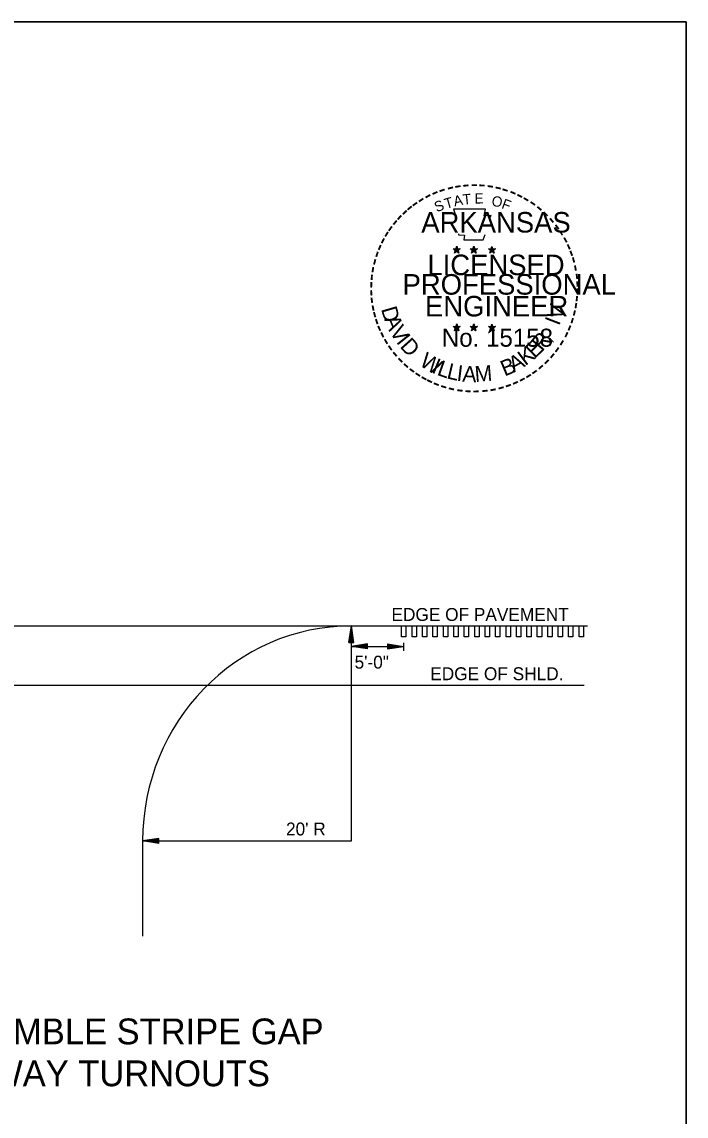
# Model space of a CAD drawing. Extents: x 28704 to 32542, y 50360 to 59122.
# Drawn here: x 30070 to 30404, y 50922 to 51472 of the extents above; entities that cross this region are included whole.
import ezdxf

# ---------------------------------------------------------------- set-up
doc = ezdxf.new("R2010")
doc.units = 0
for name, color, linetype in [('Default', 7, 'Continuous'), ('R_Alt Surface', 7, 'Continuous'), ('R_Alt Surface Annot', 7, 'Continuous'), ('R_Border Prem', 7, 'Continuous')]:
    doc.layers.add(name, color=color, linetype=linetype)

msp = doc.modelspace()

# ---------------------------------------------------------------- linework, layer by layer
at = {"layer": 'Default'}
for points in [[(28703.96, 51472.36), (30403.96, 51472.36), (30403.96, 50372.36), (28703.96, 50372.36)], [(28703.96, 51472.36), (28703.96, 50372.36), (30403.96, 50372.36), (30403.96, 51472.36)]]:
    msp.add_lwpolyline(points, close=True, dxfattribs=at)
at = {"layer": 'R_Alt Surface'}
for p, q in [((29815.67, 51168.75), (30354.46, 51168.75)), ((30235.69, 51060.65), (30235.69, 51168.75)), ((30235.69, 51158.44), (30261.92, 51158.44)), ((30261.92, 51160.3), (30261.92, 51156.3)), ((29813.93, 51138.97), (30352.72, 51138.97)), ((30130.72, 51060.65), (30130.72, 51012.79)), ((30130.72, 51060.65), (30235.69, 51060.65))]:
    msp.add_line(p, q, dxfattribs=at)
for points in [[(30260.93, 51163.33), (30260.93, 51168.74), (30263.12, 51168.74), (30263.12, 51163.33), (30260.93, 51163.33)], [(30266.18, 51163.33), (30266.18, 51168.74), (30268.37, 51168.74), (30268.37, 51163.33), (30266.18, 51163.33)], [(30271.43, 51163.33), (30271.43, 51168.74), (30273.61, 51168.74), (30273.61, 51163.33), (30271.43, 51163.33)], [(30276.68, 51163.33), (30276.68, 51168.74), (30278.86, 51168.74), (30278.86, 51163.33), (30276.68, 51163.33)], [(30281.92, 51163.33), (30281.92, 51168.74), (30284.11, 51168.74), (30284.11, 51163.33), (30281.92, 51163.33)], [(30287.17, 51163.33), (30287.17, 51168.74), (30289.36, 51168.74), (30289.36, 51163.33), (30287.17, 51163.33)], [(30292.42, 51163.33), (30292.42, 51168.74), (30294.6, 51168.74), (30294.6, 51163.33), (30292.42, 51163.33)], [(30297.66, 51163.33), (30297.66, 51168.74), (30299.85, 51168.74), (30299.85, 51163.33), (30297.66, 51163.33)], [(30302.91, 51163.33), (30302.91, 51168.74), (30305.1, 51168.74), (30305.1, 51163.33), (30302.91, 51163.33)], [(30308.16, 51163.33), (30308.16, 51168.74), (30310.35, 51168.74), (30310.35, 51163.33), (30308.16, 51163.33)], [(30313.41, 51163.33), (30313.41, 51168.74), (30315.59, 51168.74), (30315.59, 51163.33), (30313.41, 51163.33)], [(30318.65, 51163.33), (30318.65, 51168.74), (30320.84, 51168.74), (30320.84, 51163.33), (30318.65, 51163.33)], [(30323.9, 51163.33), (30323.9, 51168.74), (30326.09, 51168.74), (30326.09, 51163.33), (30323.9, 51163.33)], [(30329.15, 51163.33), (30329.15, 51168.74), (30331.34, 51168.74), (30331.34, 51163.33), (30329.15, 51163.33)], [(30334.4, 51163.33), (30334.4, 51168.74), (30336.58, 51168.74), (30336.58, 51163.33), (30334.4, 51163.33)], [(30339.64, 51163.33), (30339.64, 51168.74), (30341.83, 51168.74), (30341.83, 51163.33), (30339.64, 51163.33)], [(30344.89, 51163.33), (30344.89, 51168.74), (30347.08, 51168.74), (30347.08, 51163.33), (30344.89, 51163.33)], [(30350.14, 51163.33), (30350.14, 51168.74), (30352.32, 51168.74), (30352.32, 51163.33), (30350.14, 51163.33)]]:
    msp.add_lwpolyline(points, dxfattribs=at)
msp.add_ellipse((30235.69, 51060.65), major_axis=(0, 108.1), ratio=0.970998, start_param=0, end_param=1.570796, dxfattribs=at)
at = {"layer": 'R_Alt Surface Annot'}
for p, q in [((30234.47, 51160.38), (30235.69, 51168.75)), ((30234.47, 51160.38), (30235.69, 51168.75)), ((30234.67, 51160.38), (30235.69, 51167.35)), ((30234.67, 51160.38), (30235.69, 51167.35)), ((30236.9, 51160.38), (30235.69, 51168.75)), ((30236.9, 51160.38), (30235.69, 51168.75)), ((30236.7, 51160.38), (30235.69, 51167.35)), ((30236.7, 51160.38), (30235.69, 51167.35)), ((30234.88, 51160.38), (30235.69, 51165.91)), ((30234.88, 51160.38), (30235.69, 51165.91)), ((30235.08, 51160.38), (30235.69, 51164.52)), ((30235.08, 51160.38), (30235.69, 51164.52)), ((30235.29, 51160.38), (30235.69, 51163.1)), ((30235.29, 51160.38), (30235.69, 51163.1)), ((30235.49, 51160.38), (30235.69, 51161.7)), ((30235.49, 51160.38), (30235.69, 51161.7)), ((30236.49, 51160.38), (30235.69, 51165.91)), ((30236.49, 51160.38), (30235.69, 51165.91)), ((30236.29, 51160.38), (30235.69, 51164.52)), ((30236.29, 51160.38), (30235.69, 51164.52)), ((30236.08, 51160.38), (30235.69, 51163.1)), ((30236.08, 51160.38), (30235.69, 51163.1)), ((30235.88, 51160.38), (30235.69, 51161.7)), ((30235.88, 51160.38), (30235.69, 51161.7)), ((30234.47, 51160.38), (30236.9, 51160.38)), ((30234.47, 51160.38), (30236.9, 51160.38)), ((30243.81, 51159.69), (30235.69, 51158.44)), ((30243.81, 51157.18), (30235.69, 51158.44)), ((30243.81, 51159.48), (30237.04, 51158.44)), ((30243.81, 51157.39), (30237.04, 51158.44)), ((30243.81, 51159.27), (30238.44, 51158.44)), ((30243.81, 51157.6), (30238.44, 51158.44)), ((30243.81, 51159.06), (30239.79, 51158.44)), ((30243.81, 51157.81), (30239.79, 51158.44)), ((30243.81, 51158.85), (30241.17, 51158.44)), ((30243.81, 51158.03), (30241.17, 51158.44)), ((30243.81, 51158.63), (30242.53, 51158.44)), ((30243.81, 51158.24), (30242.53, 51158.44)), ((30243.81, 51157.18), (30243.81, 51159.69)), ((30253.8, 51159.69), (30261.92, 51158.44)), ((30253.8, 51159.69), (30253.8, 51157.18)), ((30253.8, 51159.48), (30260.57, 51158.44)), ((30253.8, 51159.27), (30259.17, 51158.44)), ((30253.8, 51159.06), (30257.81, 51158.44)), ((30253.8, 51158.84), (30256.44, 51158.44)), ((30253.8, 51158.63), (30255.08, 51158.44)), ((30253.8, 51157.18), (30261.92, 51158.44)), ((30253.8, 51158.03), (30256.44, 51158.44)), ((30253.8, 51157.6), (30259.17, 51158.44)), ((30253.8, 51157.39), (30260.57, 51158.44)), ((30253.8, 51157.81), (30257.81, 51158.44)), ((30253.8, 51158.24), (30255.08, 51158.44)), ((30138.85, 51061.91), (30130.72, 51060.65)), ((30138.85, 51061.91), (30130.72, 51060.65)), ((30138.85, 51059.4), (30130.72, 51060.65)), ((30138.85, 51059.4), (30130.72, 51060.65)), ((30138.85, 51061.7), (30132.08, 51060.65)), ((30138.85, 51061.7), (30132.08, 51060.65)), ((30138.85, 51059.61), (30132.08, 51060.65)), ((30138.85, 51059.61), (30132.08, 51060.65)), ((30138.85, 51061.49), (30133.48, 51060.65)), ((30138.85, 51061.49), (30133.48, 51060.65)), ((30138.85, 51059.82), (30133.48, 51060.65)), ((30138.85, 51059.82), (30133.48, 51060.65)), ((30138.85, 51061.28), (30134.83, 51060.65)), ((30138.85, 51061.28), (30134.83, 51060.65)), ((30138.85, 51060.03), (30134.83, 51060.65)), ((30138.85, 51060.03), (30134.83, 51060.65)), ((30138.85, 51061.06), (30136.21, 51060.65)), ((30138.85, 51061.06), (30136.21, 51060.65)), ((30138.85, 51060.25), (30136.21, 51060.65)), ((30138.85, 51060.25), (30136.21, 51060.65)), ((30138.85, 51060.85), (30137.57, 51060.65)), ((30138.85, 51060.85), (30137.57, 51060.65)), ((30138.85, 51060.46), (30137.57, 51060.65)), ((30138.85, 51060.46), (30137.57, 51060.65)), ((30138.85, 51059.4), (30138.85, 51061.91)), ((30138.85, 51059.4), (30138.85, 51061.91))]:
    msp.add_line(p, q, dxfattribs=at)
at = {"layer": 'R_Border Prem'}
for p, q in [((30288.63, 51359.58), (30288.42, 51358.28)), ((30288.63, 51357.7), (30288.63, 51359.58)), ((30288.63, 51359.58), (30288.89, 51358.29)), ((30297.25, 51359.58), (30297.03, 51358.28)), ((30297.25, 51357.7), (30297.25, 51359.58)), ((30297.25, 51359.58), (30297.5, 51358.29)), ((30306.34, 51359.52), (30306.13, 51358.22)), ((30306.34, 51357.63), (30306.34, 51359.52)), ((30306.34, 51359.52), (30306.59, 51358.23)), ((30286.84, 51358.27), (30288.63, 51357.7)), ((30286.84, 51358.27), (30288.14, 51358.04)), ((30286.84, 51358.27), (30288.06, 51357.64)), ((30287.52, 51356.16), (30288.63, 51357.7)), ((30287.52, 51356.16), (30288.17, 51357.42)), ((30287.52, 51356.16), (30288.62, 51357.28)), ((30289.73, 51356.16), (30288.62, 51357.27)), ((30290.42, 51358.27), (30288.63, 51357.7)), ((30289.73, 51356.16), (30288.63, 51357.7)), ((30290.42, 51358.27), (30288.95, 51358.02)), ((30289.73, 51356.16), (30289.03, 51357.66)), ((30290.42, 51358.27), (30289.37, 51357.74)), ((30295.45, 51358.27), (30297.25, 51357.7)), ((30295.45, 51358.27), (30296.75, 51358.04)), ((30295.45, 51358.27), (30296.67, 51357.64)), ((30296.13, 51356.16), (30297.25, 51357.7)), ((30296.13, 51356.16), (30296.78, 51357.42)), ((30296.13, 51356.16), (30297.24, 51357.28)), ((30298.34, 51356.16), (30297.24, 51357.27)), ((30299.04, 51358.27), (30297.25, 51357.7)), ((30298.34, 51356.16), (30297.25, 51357.7)), ((30299.04, 51358.27), (30297.56, 51358.02)), ((30298.34, 51356.16), (30297.64, 51357.66)), ((30299.04, 51358.27), (30297.98, 51357.74)), ((30304.54, 51358.21), (30306.34, 51357.63)), ((30304.54, 51358.21), (30305.85, 51357.97)), ((30304.54, 51358.21), (30305.76, 51357.58)), ((30305.23, 51356.1), (30306.34, 51357.63)), ((30305.23, 51356.1), (30305.88, 51357.36)), ((30305.23, 51356.1), (30306.33, 51357.22)), ((30307.44, 51356.1), (30306.33, 51357.21)), ((30308.13, 51358.21), (30306.34, 51357.63)), ((30307.44, 51356.1), (30306.34, 51357.63)), ((30308.13, 51358.21), (30306.66, 51357.95)), ((30307.44, 51356.1), (30306.73, 51357.6)), ((30308.13, 51358.21), (30307.08, 51357.68)), ((30288.61, 51320.53), (30288.4, 51319.23)), ((30288.61, 51318.65), (30288.61, 51320.53)), ((30288.61, 51320.53), (30288.87, 51319.24)), ((30297.22, 51320.53), (30297.01, 51319.23)), ((30297.22, 51318.65), (30297.22, 51320.53)), ((30297.22, 51320.53), (30297.47, 51319.24)), ((30286.81, 51319.22), (30288.61, 51318.65)), ((30286.81, 51319.22), (30288.12, 51318.99)), ((30286.81, 51319.22), (30288.04, 51318.59)), ((30287.5, 51317.12), (30288.61, 51318.65)), ((30287.5, 51317.12), (30288.15, 51318.37)), ((30287.5, 51317.12), (30288.6, 51318.24)), ((30289.71, 51317.12), (30288.6, 51318.22)), ((30290.4, 51319.22), (30288.61, 51318.65)), ((30289.71, 51317.12), (30288.61, 51318.65)), ((30290.4, 51319.22), (30288.93, 51318.97)), ((30289.71, 51317.12), (30289.01, 51318.62)), ((30290.4, 51319.22), (30289.35, 51318.69)), ((30295.42, 51319.22), (30297.22, 51318.65)), ((30295.42, 51319.22), (30296.73, 51318.99)), ((30295.42, 51319.22), (30296.64, 51318.59)), ((30296.11, 51317.12), (30297.22, 51318.65)), ((30296.11, 51317.12), (30296.76, 51318.37)), ((30296.11, 51317.12), (30297.21, 51318.24)), ((30298.32, 51317.12), (30297.21, 51318.22)), ((30299.01, 51319.22), (30297.22, 51318.65)), ((30298.32, 51317.12), (30297.22, 51318.65)), ((30299.01, 51319.22), (30297.53, 51318.97)), ((30298.32, 51317.12), (30297.61, 51318.62)), ((30299.01, 51319.22), (30297.96, 51318.69)), ((30304.53, 51319.17), (30306.33, 51318.6)), ((30304.53, 51319.17), (30305.84, 51318.94)), ((30304.53, 51319.17), (30305.75, 51318.54)), ((30305.22, 51317.06), (30306.33, 51318.6)), ((30305.22, 51317.06), (30305.87, 51318.32)), ((30305.22, 51317.06), (30306.32, 51318.18)), ((30306.33, 51320.48), (30306.12, 51319.18)), ((30307.43, 51317.06), (30306.32, 51318.17)), ((30306.33, 51318.6), (30306.33, 51320.48)), ((30306.33, 51320.48), (30306.58, 51319.19)), ((30308.12, 51319.17), (30306.33, 51318.6)), ((30307.43, 51317.06), (30306.33, 51318.6)), ((30308.12, 51319.17), (30306.65, 51318.92)), ((30307.43, 51317.06), (30306.72, 51318.57)), ((30308.12, 51319.17), (30307.07, 51318.64))]:
    msp.add_line(p, q, dxfattribs=at)
for points in [[(30287.05, 51378.26), (30288.43, 51374)], [(30305.15, 51373.51), (30305.88, 51374.97), (30302.35, 51374.85), (30303.11, 51378.26), (30287.05, 51378.26)], [(30289.58, 51365.77), (30289.58, 51365.32), (30292.49, 51365.22), (30292.21, 51362.79), (30301.85, 51362.79), (30302.89, 51365.55)], [(30288.63, 51359.58), (30289.73, 51356.16), (30286.84, 51358.27), (30290.42, 51358.27), (30287.52, 51356.16), (30288.63, 51359.58)], [(30297.25, 51359.58), (30298.34, 51356.16), (30295.45, 51358.27), (30299.04, 51358.27), (30296.13, 51356.16), (30297.25, 51359.58)], [(30306.34, 51359.52), (30307.44, 51356.1), (30304.54, 51358.21), (30308.13, 51358.21), (30305.23, 51356.1), (30306.34, 51359.52)], [(30288.61, 51320.53), (30289.71, 51317.12), (30286.81, 51319.22), (30290.4, 51319.22), (30287.5, 51317.12), (30288.61, 51320.53)], [(30297.22, 51320.53), (30298.32, 51317.12), (30295.42, 51319.22), (30299.01, 51319.22), (30296.11, 51317.12), (30297.22, 51320.53)], [(30306.33, 51320.48), (30307.43, 51317.06), (30304.53, 51319.17), (30308.12, 51319.17), (30305.22, 51317.06), (30306.33, 51320.48)]]:
    msp.add_lwpolyline(points, dxfattribs=at)
for centre, radius in [((30288.63, 51357.69), 0.888), ((30288.63, 51357.69), 0.745), ((30288.63, 51357.69), 0.597), ((30288.63, 51357.69), 0.511), ((30288.63, 51357.69), 0.385), ((30288.63, 51357.69), 0.255), ((30288.63, 51357.69), 0.153), ((30297.24, 51357.69), 0.888), ((30297.24, 51357.69), 0.745), ((30297.24, 51357.69), 0.597), ((30297.24, 51357.69), 0.511), ((30297.24, 51357.69), 0.385), ((30297.24, 51357.69), 0.255), ((30297.24, 51357.69), 0.153), ((30306.34, 51357.63), 0.888), ((30306.34, 51357.63), 0.745), ((30306.34, 51357.63), 0.597), ((30306.34, 51357.63), 0.511), ((30306.34, 51357.63), 0.385), ((30306.34, 51357.63), 0.255), ((30306.34, 51357.63), 0.153), ((30288.61, 51318.64), 0.888), ((30288.61, 51318.64), 0.745), ((30288.61, 51318.64), 0.597), ((30288.61, 51318.64), 0.511), ((30288.61, 51318.64), 0.385), ((30288.61, 51318.64), 0.255), ((30288.61, 51318.64), 0.153), ((30297.21, 51318.64), 0.888), ((30297.21, 51318.64), 0.745), ((30297.21, 51318.64), 0.597), ((30297.21, 51318.64), 0.511), ((30297.21, 51318.64), 0.385), ((30297.21, 51318.64), 0.255), ((30297.21, 51318.64), 0.153), ((30306.33, 51318.59), 0.888), ((30306.33, 51318.59), 0.745), ((30306.33, 51318.59), 0.597), ((30306.33, 51318.59), 0.511), ((30306.33, 51318.59), 0.385), ((30306.33, 51318.59), 0.255), ((30306.33, 51318.59), 0.153)]:
    msp.add_circle(centre, radius, dxfattribs=at)

# ---------------------------------------------------------------- texts
at = {"layer": 'R_Alt Surface'}
for s, height, p in [('EDGE OF PAVEMENT', 6.485, (30255.82, 51171.25)), ('5\'-0"', 6.485, (30237.28, 51147.29)), ('EDGE OF SHLD.', 6.485, (30275.32, 51141.47)), ("20' R", 6.485, (30202.8, 51063.44)), ('DETAIL FOR RUMBLE STRIPE GAP', 12.9699, (29933.57, 50958.45)), ('AT DRIVEWAY TURNOUTS', 12.9699, (29974.08, 50937.37))]:
    msp.add_text(s, height=height, dxfattribs=at).set_placement(p)
at = {"layer": 'R_Border Prem'}
for s, height, rotation, p in [('-', 8.25, 24.3072, (30277.32, 51382.69)), ('-', 8.25, 19.1761, (30280.59, 51384.08)), ('-', 8.25, 13.6302, (30284.46, 51385.32)), ('-', 8.25, 10.2193, (30287.95, 51386.15)), ('-', 8.25, 5.8968, (30291.71, 51386.72)), ('-', 8.25, 0.1862, (30295.69, 51387.09)), ('-', 8.25, 357.743, (30299.42, 51387.02)), ('-', 8.25, 352.1617, (30303.26, 51386.74)), ('-', 8.25, 347.2049, (30306.96, 51386.15)), ('-', 8.25, 342.3362, (30310.24, 51385.35)), ('-', 8.25, 337.8551, (30314.03, 51384.2)), ('-', 8.25, 36.2317, (30268, 51377.11)), ('-', 8.25, 34.0636, (30270.98, 51379.15)), ('-', 8.25, 28.7918, (30274.06, 51381.05)), ('S', 5.16, 21.594, (30278.56, 51376.6)), ('T', 5.16, 16.4036, (30283.28, 51378.31)), ('A', 5.16, 11.2132, (30287.54, 51379.6)), ('T', 5.16, 6.0228, (30291.91, 51380.46)), ('E', 5.16, 0.8323, (30297.61, 51381.03)), ('O', 5.16, 350.4515, (30305.88, 51379.95)), ('F', 5.16, 340.0707, (30310.8, 51378.77)), ('-', 8.25, 334.1211, (30317.28, 51382.8)), ('-', 8.25, 329.6409, (30320.27, 51381.34)), ('-', 8.25, 325.8627, (30323.58, 51379.48)), ('-', 8.25, 42.9622, (30263.31, 51373.01)), ('-', 8.25, 38.9507, (30265.54, 51375.16)), ('-', 8.25, 320.5297, (30326.73, 51377.28)), ('-', 8.25, 315.5786, (30329.82, 51374.77)), ('-', 8.25, 50.6142, (30258.92, 51368.04)), ('-', 8.25, 48.4231, (30261, 51370.55)), ('-', 8.25, 309.8797, (30332.75, 51371.93)), ('-', 8.25, 306.6522, (30335.46, 51368.83)), ('-', 8.25, 58.0706, (30255.12, 51362.4)), ('-', 8.25, 54.2325, (30256.79, 51365.12)), ('-', 7.22, 303.6753, (30337.96, 51365.9)), ('-', 8.25, 67.7743, (30252.17, 51356.08)), ('-', 8.25, 62.8713, (30253.5, 51359.23)), ('-', 8.25, 299.6684, (30339.61, 51362.77)), ('-', 8.25, 294.6628, (30341.28, 51359.61)), ('-', 8.25, 72.3945, (30251.04, 51352.83)), ('-', 8.25, 290.5728, (30342.6, 51356.64)), ('-', 8.25, 285.1233, (30343.81, 51353.65)), ('-', 8.25, 81.2013, (30249.34, 51345.48)), ('-', 8.25, 75.461, (30250.02, 51349.15)), ('-', 8.25, 280.5493, (30344.84, 51349.82)), ('-', 8.25, 85.1863, (30248.95, 51341.91)), ('-', 8.25, 276.5962, (30345.68, 51345.86)), ('-', 8.25, 94.1959, (30249, 51334.56)), ('-', 8.25, 89.0622, (30248.82, 51338.3)), ('-', 8.25, 274.3301, (30345.99, 51342.14)), ('-', 8.25, 269.9407, (30346.16, 51338.88)), ('-', 8.25, 98.9479, (30249.37, 51331.12)), ('-', 8.25, 263.5172, (30346.06, 51335.45)), ('-', 8.25, 101.7149, (30250.07, 51327.34)), ('-', 8.25, 105.4578, (30250.91, 51324.27)), ('D', 7.94, 286.2848, (30250.53, 51328.05)), ('V', 7.94, 72.6573, (30341.24, 51322.07)), ('-', 8.25, 255.7626, (30345.13, 51328.58)), ('-', 8.25, 260.9953, (30345.7, 51332.07)), ('-', 8.25, 109.0874, (30252.01, 51321.02)), ('A', 7.94, 292.7835, (30252.04, 51322.89)), ('V', 7.94, 300.7936, (30254.69, 51316.81)), ('I', 7.94, 69.0301, (30340.09, 51319.29)), ('-', 8.25, 252.8681, (30344.2, 51324.87)), ('-', 8.25, 114.0643, (30253.32, 51317.95)), ('-', 8.25, 115.7289, (30254.9, 51314.76)), ('I', 7.94, 308.3502, (30257.94, 51311.46)), ('R', 7.94, 50.3651, (30331.58, 51306.46)), ('-', 8.25, 244.6197, (30341.7, 51318.15)), ('-', 8.25, 247.8887, (30343.05, 51321.4)), ('-', 8.25, 120.4471, (30256.74, 51311.74)), ('-', 8.25, 125.8934, (30258.82, 51308.85)), ('D', 7.94, 311.9774, (30259.75, 51309.06)), ('K', 7.94, 36.9143, (30323.11, 51299.25)), ('E', 7.94, 44.0175, (30327.8, 51302.81)), (',', 7.94, 57.4684, (30335.31, 51311.01)), ('-', 8.25, 239.0712, (30339.67, 51314.28)), ('-', 8.25, 130.7181, (30261.2, 51306)), ('W', 7.94, 328.0731, (30269.43, 51299.95)), ('A', 7.94, 28.9042, (30317.35, 51295.97)), ('-', 8.25, 231.2538, (30335.38, 51307.99)), ('-', 8.25, 233.8452, (30337.59, 51310.91)), ('-', 8.25, 134.2238, (30263.86, 51303.19)), ('-', 8.25, 138.9338, (30266.57, 51300.8)), ('I', 7.94, 336.6877, (30275.56, 51296.29)), ('L', 7.94, 340.3149, (30278.29, 51295.04)), ('L', 7.94, 346.6625, (30283.23, 51293.26)), ('I', 7.94, 353.0101, (30288.35, 51292.04)), ('A', 7.94, 356.6373, (30291.32, 51291.6)), ('M', 7.94, 4.6473, (30297.95, 51291.3)), ('B', 7.94, 22.8589, (30312.73, 51294.04)), ('-', 8.25, 221.0851, (30330.21, 51302.46)), ('-', 8.25, 225.7653, (30332.91, 51305.08)), ('-', 8.25, 144.6463, (30269.44, 51298.7)), ('-', 8.25, 148.0898, (30272.33, 51296.79)), ('-', 8.25, 151.5704, (30275.32, 51295.11)), ('-', 8.25, 207.3568, (30321.75, 51296.24)), ('-', 8.25, 212.2491, (30324.63, 51298.03)), ('-', 8.25, 215.7363, (30327.38, 51300.02)), ('-', 8.25, 154.6002, (30278.01, 51293.84)), ('-', 8.25, 158.5612, (30281.22, 51292.53)), ('-', 8.25, 162.7983, (30284.77, 51291.43)), ('-', 8.25, 167.5555, (30288.45, 51290.59)), ('-', 8.25, 173.1155, (30292.43, 51290.02)), ('-', 8.25, 191.2858, (30308.09, 51290.92)), ('-', 8.25, 195.4743, (30311.85, 51291.94)), ('-', 8.25, 199.4643, (30315.28, 51293.17)), ('-', 8.25, 204.2516, (30318.53, 51294.6)), ('-', 8.25, 176.5183, (30296.29, 51289.75)), ('-', 8.25, 181.5918, (30300.13, 51289.84)), ('-', 8.25, 185.8167, (30304.3, 51290.24))]:
    msp.add_text(s, height=height, rotation=rotation, dxfattribs=at).set_placement(p)
for s, height, p in [('ARKANSAS', 10.312, (30270.82, 51366.47)), ('LICENSED', 10.312, (30273.9, 51345.07)), ('PROFESSIONAL', 10.3125, (30261.4, 51335.26)), ('ENGINEER', 10.312, (30272.68, 51324.3)), ('No. 15158', 9.06, (30281.14, 51309.08)), ('AAMU', 0.000103, (30296.88, 51291.27))]:
    msp.add_text(s, height=height, dxfattribs=at).set_placement(p)

doc.saveas('drawing.dxf')
